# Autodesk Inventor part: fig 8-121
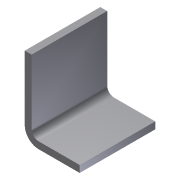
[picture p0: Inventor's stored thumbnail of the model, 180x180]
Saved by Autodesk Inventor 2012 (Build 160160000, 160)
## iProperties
Created: 2009-09
Part Number: fig 8-121
Document SubType Name: Modeling
Designer: Sham
Density: 1 g/cm^3
Material: Default
Author: Sham
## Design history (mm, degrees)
sketch "Sketch1"
  geometry: L1 (-33.976, 22)-(0, 22); L2 (0, 22)-(0, 0); L3 (0, 0)-(-33.976, 0); L4 (-33.976, 0)-(-33.976, 22)
  constraints: 8 end point, 2 parallel, 1 horizontal, 1 perpendicular
extrude "Extrusion1" new body sketch "Sketch1" distance "d0" = 2; taper "d1" = 0 deg
sketch "Sketch2"
  geometry: L1 (-12, 22)-(-12, 0)
  constraints: 2 end point
feature "Bend Part1" sketch "Sketch2" dims "d5" = 90 deg, "d6" = 2
body "Solid1"
